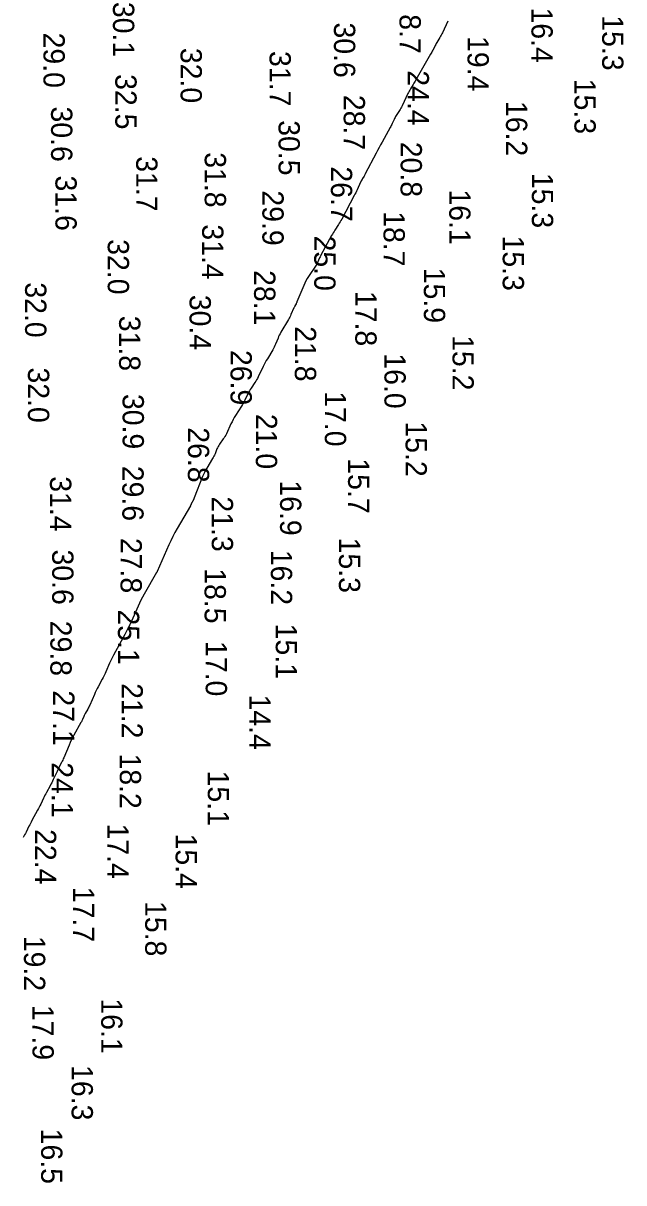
# Model space of a CAD drawing. Extents: x 1178573 to 1187098, y 693282 to 751751.
# Drawn here: x 1179872 to 1180224, y 710887 to 711569 of the extents above; entities that cross this region are included whole.
import ezdxf

# ---------------------------------------------------------------- set-up
doc = ezdxf.new("R2010")
doc.units = 0
doc.layers.add('V-HYDS-MAJR', color=7, linetype='Continuous')
doc.layers.add('V-HYDS-SOUN', color=7, linetype='Continuous')

msp = doc.modelspace()

# ---------------------------------------------------------------- linework, layer by layer
at = {"layer": 'V-HYDS-MAJR'}
msp.add_lwpolyline([(1180121.16, 711570.19), (1180117.9, 711563.4), (1180117.55, 711562.69), (1180117.18, 711561.99), (1180116.8, 711561.3), (1180116.4, 711560.62), (1180114.62, 711557.66), (1180114.29, 711557.1), (1180113.98, 711556.53), (1180113.67, 711555.96), (1180113.38, 711555.38), (1180112.23, 711553.04), (1180111.94, 711552.45), (1180111.64, 711551.87), (1180111.33, 711551.3), (1180111.01, 711550.73), (1180102.35, 711535.65), (1180101.96, 711534.97), (1180101.57, 711534.3), (1180101.17, 711533.63), (1180100.77, 711532.96), (1180099.14, 711530.3), (1180098.75, 711529.63), (1180098.37, 711528.95), (1180098.01, 711528.26), (1180097.66, 711527.56), (1180094.27, 711520.43), (1180093.91, 711519.71), (1180093.53, 711519), (1180093.12, 711518.3), (1180092.7, 711517.61), (1180090.75, 711514.62), (1180090.41, 711514.07), (1180090.09, 711513.51), (1180089.79, 711512.94), (1180089.51, 711512.36), (1180088.44, 711510.02), (1180088.17, 711509.43), (1180087.89, 711508.86), (1180087.59, 711508.28), (1180087.28, 711507.72), (1180082.47, 711499.11), (1180081.56, 711497.48), (1180080.68, 711495.85), (1180079.8, 711494.21), (1180078.93, 711492.56), (1180072.6, 711480.4), (1180072.43, 711480.08), (1180072.26, 711479.76), (1180072.08, 711479.44), (1180071.9, 711479.13), (1180071.01, 711477.58), (1180070.91, 711477.41), (1180070.81, 711477.25), (1180070.72, 711477.08), (1180070.62, 711476.92), (1180070.22, 711476.26), (1180070.13, 711476.09), (1180070.04, 711475.92), (1180069.95, 711475.75), (1180069.87, 711475.58), (1180067.75, 711470.97), (1180067.36, 711470.15), (1180066.96, 711469.33), (1180066.55, 711468.52), (1180066.13, 711467.71), (1180058.75, 711453.82), (1180058.29, 711452.99), (1180057.82, 711452.17), (1180057.33, 711451.36), (1180056.82, 711450.56), (1180054.75, 711447.38), (1180054.24, 711446.58), (1180053.74, 711445.77), (1180053.26, 711444.96), (1180052.8, 711444.13), (1180046.51, 711432.57), (1180046.26, 711432.09), (1180046.02, 711431.61), (1180045.79, 711431.12), (1180045.58, 711430.62), (1180044.77, 711428.63), (1180044.56, 711428.13), (1180044.32, 711427.65), (1180044.05, 711427.19), (1180043.77, 711426.73), (1180039.32, 711420.07), (1180038.51, 711418.79), (1180037.77, 711417.47), (1180037.09, 711416.13), (1180036.48, 711414.74), (1180032.49, 711405.08), (1180032.36, 711404.78), (1180032.22, 711404.48), (1180032.08, 711404.19), (1180031.92, 711403.91), (1180031.28, 711402.77), (1180031.13, 711402.49), (1180030.98, 711402.2), (1180030.83, 711401.91), (1180030.7, 711401.61), (1180028.94, 711397.67), (1180028.6, 711396.92), (1180028.23, 711396.18), (1180027.84, 711395.46), (1180027.43, 711394.74), (1180023.01, 711387.26), (1180022.55, 711386.43), (1180022.11, 711385.59), (1180021.71, 711384.73), (1180021.34, 711383.86), (1180019.92, 711380.33), (1180019.55, 711379.45), (1180019.14, 711378.6), (1180018.7, 711377.76), (1180018.22, 711376.94), (1180015.08, 711371.74), (1180014.41, 711370.6), (1180013.77, 711369.44), (1180013.15, 711368.27), (1180012.56, 711367.08), (1180009.66, 711361.01), (1180009.23, 711360.15), (1180008.76, 711359.3), (1180008.27, 711358.47), (1180007.74, 711357.65), (1180005.58, 711354.43), (1180005.05, 711353.62), (1180004.55, 711352.79), (1180004.08, 711351.94), (1180003.64, 711351.08), (1180001.82, 711347.39), (1180001.36, 711346.49), (1180000.88, 711345.6), (1180000.38, 711344.73), (1179999.85, 711343.86), (1179996.33, 711338.25), (1179995.62, 711337.08), (1179994.95, 711335.88), (1179994.31, 711334.67), (1179993.71, 711333.44), (1179990.99, 711327.6), (1179990.59, 711326.79), (1179990.16, 711326.01), (1179989.69, 711325.25), (1179989.19, 711324.51), (1179986.97, 711321.38), (1179986.54, 711320.74), (1179986.15, 711320.07), (1179985.8, 711319.38), (1179985.49, 711318.67), (1179984.33, 711315.78), (1179984.03, 711315.07), (1179983.7, 711314.37), (1179983.34, 711313.68), (1179982.95, 711313.01), (1179979.48, 711307.3), (1179978.8, 711306.11), (1179978.16, 711304.9), (1179977.58, 711303.66), (1179977.05, 711302.4), (1179972.11, 711289.92), (1179972.01, 711289.68), (1179971.91, 711289.44), (1179971.81, 711289.2), (1179971.7, 711288.96), (1179971.24, 711287.99), (1179971.14, 711287.77), (1179971.03, 711287.54), (1179970.92, 711287.31), (1179970.81, 711287.09), (1179970.36, 711286.18), (1179970.25, 711285.96), (1179970.14, 711285.74), (1179970.02, 711285.52), (1179969.89, 711285.3), (1179962.12, 711271.82), (1179960.82, 711269.48), (1179959.58, 711267.12), (1179958.4, 711264.72), (1179957.28, 711262.29), (1179950.35, 711246.63), (1179950.33, 711246.6), (1179950.31, 711246.56), (1179950.29, 711246.52), (1179950.27, 711246.49), (1179950.19, 711246.33), (1179950.17, 711246.3), (1179950.16, 711246.27), (1179950.14, 711246.23), (1179950.12, 711246.2), (1179950.06, 711246.06), (1179950.04, 711246.03), (1179950.03, 711245.99), (1179950.01, 711245.96), (1179949.99, 711245.93), (1179942.75, 711233.29), (1179941.78, 711231.54), (1179940.85, 711229.77), (1179939.97, 711227.97), (1179939.13, 711226.15), (1179934.42, 711215.61), (1179934.32, 711215.4), (1179934.22, 711215.18), (1179934.11, 711214.97), (1179934, 711214.76), (1179933.56, 711213.92), (1179933.45, 711213.71), (1179933.35, 711213.5), (1179933.24, 711213.28), (1179933.14, 711213.07), (1179932.21, 711211.11), (1179932.02, 711210.72), (1179931.83, 711210.32), (1179931.62, 711209.93), (1179931.41, 711209.55), (1179924.68, 711197.4), (1179924.06, 711196.24), (1179923.46, 711195.07), (1179922.9, 711193.88), (1179922.36, 711192.68), (1179920.21, 711187.7), (1179919.71, 711186.56), (1179919.18, 711185.43), (1179918.62, 711184.32), (1179918.04, 711183.22), (1179915.68, 711178.83), (1179915.1, 711177.73), (1179914.54, 711176.62), (1179914.01, 711175.5), (1179913.5, 711174.36), (1179910.76, 711168.07), (1179910.49, 711167.48), (1179910.2, 711166.89), (1179909.89, 711166.31), (1179909.56, 711165.73), (1179908.05, 711163.18), (1179907.81, 711162.75), (1179907.59, 711162.32), (1179907.38, 711161.88), (1179907.18, 711161.43), (1179906.44, 711159.61), (1179906.25, 711159.16), (1179906.04, 711158.72), (1179905.82, 711158.28), (1179905.59, 711157.85), (1179901.35, 711150.28), (1179900.6, 711148.87), (1179899.88, 711147.45), (1179899.2, 711146.01), (1179898.57, 711144.55), (1179895.46, 711137.11), (1179895.16, 711136.42), (1179894.85, 711135.73), (1179894.53, 711135.06), (1179894.2, 711134.38), (1179892.84, 711131.7), (1179892.51, 711131.03), (1179892.17, 711130.36), (1179891.85, 711129.69), (1179891.52, 711129.01), (1179889.3, 711124.31), (1179888.85, 711123.36), (1179888.38, 711122.42), (1179887.9, 711121.49), (1179887.41, 711120.57), (1179885.34, 711116.75), (1179884.88, 711115.89), (1179884.43, 711115.03), (1179884, 711114.16), (1179883.58, 711113.28), (1179881.92, 711109.77), (1179881.5, 711108.89), (1179881.06, 711108.03), (1179880.61, 711107.16), (1179880.15, 711106.31), (1179876.77, 711100.12), (1179876.32, 711099.3), (1179875.88, 711098.46), (1179875.46, 711097.63), (1179875.03, 711096.78), (1179873.37, 711093.41), (1179872.94, 711092.57), (1179872.5, 711091.74), (1179872.04, 711090.92), (1179871.56, 711090.11)], dxfattribs=at)

# ---------------------------------------------------------------- texts
at = {"layer": 'V-HYDS-SOUN'}
for s, p in [('30.1 ', (1179924.39, 711581.52)), ('28.7 ', (1180092.71, 711583.56)), ('16.4 ', (1180170.21, 711578.22)), ('15.3 ', (1180211.77, 711573.65)), ('30.6 ', (1180054.2, 711569.42)), ('29.0 ', (1179883.56, 711563.46)), ('19.4 ', (1180132.67, 711561.43)), ('32.0 ', (1179964.1, 711554.5)), ('31.7 ', (1180016.37, 711552.66)), ('32.5 ', (1179925.76, 711539.05)), ('24.4 ', (1180097.5, 711541.28)), ('15.3 ', (1180195.47, 711536.32)), ('28.7 ', (1180059.94, 711526.87)), ('30.6 ', (1179888.02, 711520.01)), ('16.2 ', (1180155.27, 711523.29)), ('30.5 ', (1180021.66, 711511.95)), ('20.8 ', (1180093.38, 711499.28)), ('31.7 ', (1179938.02, 711490.75)), ('31.8 ', (1179978.29, 711493.11)), ('26.7 ', (1180052.42, 711484.81)), ('31.6 ', (1179890.58, 711479.43)), ('15.3 ', (1180170.47, 711481)), ('29.9 ', (1180012.15, 711470.7)), ('16.1 ', (1180121.93, 711471.25)), ('18.7 ', (1180083.33, 711458.46)), ('31.4 ', (1179976.77, 711450.73)), ('25.0 ', (1180042.62, 711444.14)), ('15.3 ', (1180153.34, 711444.13)), ('32.0 ', (1179921.32, 711441.97)), ('28.1 ', (1180007.29, 711423.81)), ('15.9 ', (1180107.03, 711425.2)), ('32.0 ', (1179872.77, 711416.64)), ('30.4 ', (1179969.39, 711409.29)), ('17.8 ', (1180066.74, 711411.58)), ('31.8 ', (1179927.99, 711396.98)), ('21.8 ', (1180031.24, 711390.81)), ('15.2 ', (1180123.84, 711385.59)), ('26.9 ', (1179993.45, 711376.87)), ('16.0 ', (1180083.86, 711374.88)), ('32.0 ', (1179874.44, 711366.58)), ('30.9 ', (1179930.06, 711351.02)), ('17.0 ', (1180048.85, 711352.6)), ('21.0 ', (1180008.33, 711339.31)), ('15.2 ', (1180096.28, 711334.87)), ('26.8 ', (1179968.41, 711331.4)), ('29.6 ', (1179929.89, 711308.76)), ('15.7 ', (1180062.5, 711313.15)), ('31.4 ', (1179887.4, 711302.6)), ('16.9 ', (1180022.55, 711300.2)), ('21.3 ', (1179982.44, 711290.75)), ('27.8 ', (1179928.85, 711266.37)), ('15.3 ', (1180057.12, 711266.53)), ('30.6 ', (1179888.68, 711259.54)), ('16.2 ', (1180017.15, 711259.38)), ('18.5 ', (1179978.22, 711248.53)), ('25.1 ', (1179927.31, 711224.3)), ('29.8 ', (1179887.61, 711217.68)), ('15.1 ', (1180020.02, 711215.94)), ('17.0 ', (1179978.87, 711205.75)), ('27.1 ', (1179889.25, 711176.7)), ('21.2 ', (1179929.42, 711180.97)), ('14.4 ', (1180004.46, 711174.29)), ('18.2 ', (1179928.4, 711139.6)), ('24.1 ', (1179888.43, 711134.44)), ('15.1 ', (1179980.09, 711129.55)), ('22.4 ', (1179878.54, 711095.15)), ('17.4 ', (1179921.06, 711098.4)), ('15.4 ', (1179961.18, 711092.5)), ('17.7 ', (1179900.85, 711061.25)), ('15.8 ', (1179943.31, 711052.85)), ('19.2 ', (1179872.1, 711032.41)), ('16.1 ', (1179917.46, 710995.63)), ('17.9 ', (1179877.11, 710991.83)), ('16.3 ', (1179900.1, 710956.4)), ('16.5 ', (1179882.19, 710919.01))]:
    msp.add_text(s, height=12.5, rotation=270, dxfattribs=at).set_placement(p)

doc.saveas('drawing.dxf')
